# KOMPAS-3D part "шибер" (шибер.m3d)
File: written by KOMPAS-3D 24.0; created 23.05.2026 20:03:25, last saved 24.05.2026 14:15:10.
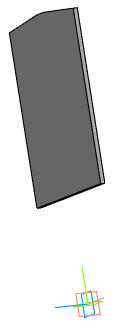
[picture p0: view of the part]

Document properties: Автор: R2D2; Полное имя файла: E:\Работа\Зайцев\GVKR1331E-1W-Fb-2P Задвижка шиберная DN.ru Ду50-300 Ру16-10-6\исходные материалы\DN300\шибер.m3d

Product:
- Part/product: шибер
    Масса: 10.072199
    Раздел спецификации: Прочие изделия
    Примечание: D040-08800

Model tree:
1. Эскиз:5  (with: Грань.Элемент выдавливания:1, Вершина.Элемент выдавливания:15)
2. Элемент выдавливания:6
     Расстояние 1 = 10

Referenced files in E:\Работа\Зайцев\GVKR1331E-1W-Fb-2P Задвижка шиберная DN.ru Ду50-300 Ру16-10-6\исходные материалы\DN300\: GVKR1331E-1W-Fb-2P Задвижка шиберная с выдвижным штоком DN.ru Ду300 Ру6.a3d
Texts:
  Затвор дисковый DN.ru Ду Ру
